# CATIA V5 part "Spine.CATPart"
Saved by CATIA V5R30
Part number: Part1
Bounding box of the stored display mesh (mm): x 97.05 to 179.832, y -8.213 to 8.213, z -51.727 to 9.115
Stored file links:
  D:\PROJECTS\CATIA V56R 2020\Resources\Parts File\c17_catia_v6_6r2020_prt\Spine.CATPart
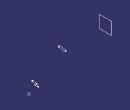
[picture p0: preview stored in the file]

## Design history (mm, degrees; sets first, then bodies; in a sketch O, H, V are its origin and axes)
Body1 (main body)
  Plane1: type Offset, RefPlane yz-plane, Offset 100
  Sketch1 on Plane1, origin (100, 0, 0), H (0, 1, 0), V (0, 0, 1)
    line L1 (-11.8744, 0) -> (18.2844, 0)
    point P1 (-11.8744, 0)
    coincidence: P1 H
    horizontal: L1 H
  Plane2: type Angle, RefPlane Plane1, Direction Sketch1, Angle 30
  Plane3: type Offset, RefPlane Plane2, Offset 75
  Plane4: type Offset, RefPlane Plane3, Offset 20
  Sketch2 on Plane4, origin (157.2724, 0, -90.8013), H (0, 1, 0), V (0.5, 0, 0.866)
    point P1 (0, 45.1194)
    coincidence: P1 V
  Sketch3 on Plane3, origin (139.9519, 0, -80.8013), H (0, 1, 0), V (0.5, 0, 0.866)
    arc A1 centre (0, 54.9362) radius 5.3671 from (5.2994, 54.0869) to (-5.2994, 54.0869) ccw
    point P1 (0, 54.9362)
    arc A2 centre (0, 42.755) radius 3.4394 from (-3.3961, 42.2107) to (3.3961, 42.2107) ccw
    point P2 (0, 42.755)
    line L1 (-5.2994, 54.0869) -> (-3.3961, 42.2107)
    line L2 (5.2994, 54.0869) -> (3.3961, 42.2107)
    coincidence: P1 V, P2 V
    tangency: L1 A1, L1 A2, L2 A1, L2 A2
  Sketch4 on Plane2, origin (75, 0, -43.3013), H (0, 1, 0), V (0.5, 0, 0.866)
    circle A1 centre (0, 52.3122) radius 8.2128
    point P1 (0, 52.3122)
    coincidence: P1 V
